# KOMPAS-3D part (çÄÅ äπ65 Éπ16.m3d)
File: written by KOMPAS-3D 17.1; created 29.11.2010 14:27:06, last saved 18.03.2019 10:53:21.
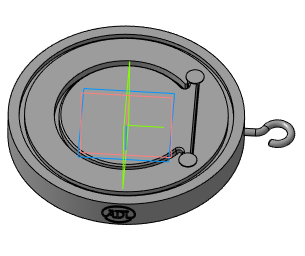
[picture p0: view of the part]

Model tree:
1. Плоскость XY
2. Плоскость ZX
3. Плоскость ZY
4. Ось X
5. Ось Y
6. Ось Z
7. Начало координат
8. Операция без истории:2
